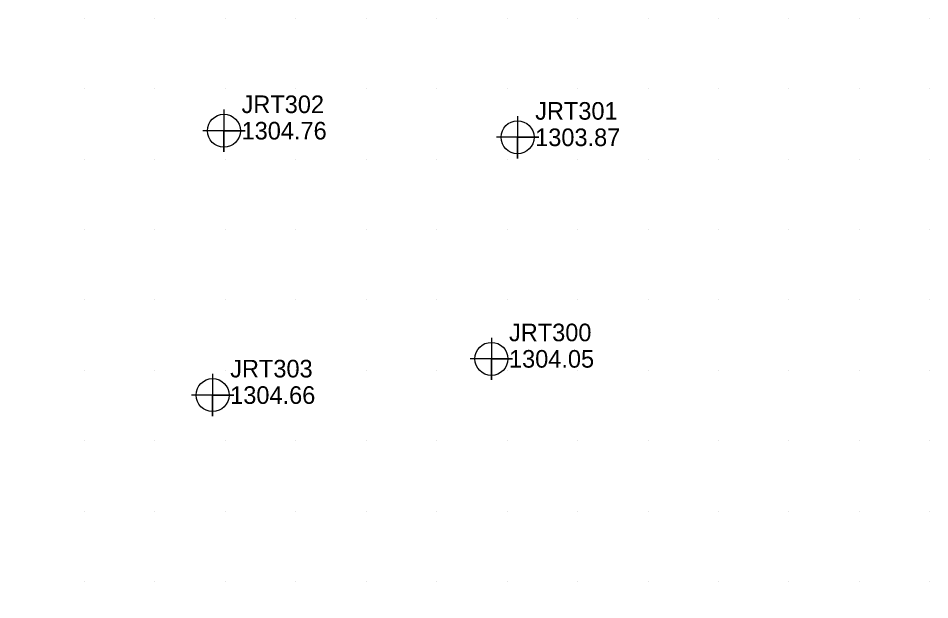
# Model space of a CAD drawing. Extents: x 1234484 to 1235382, y 695050 to 695510.
# Drawn here: x 1234800.6 to 1234930, y 695367.4 to 695450 of the extents above; entities that cross this region are included whole.
import ezdxf

# ---------------------------------------------------------------- set-up
doc = ezdxf.new("R2010")
doc.units = 0
for name, color, linetype in [('Exist DTM QL2 LIDAR Elevation Point', 7, 'Continuous'), ('Exist DTM Regular Point CELL', 7, 'Continuous'), ('Exist DTM Regular Point Cogo Elevation', 7, 'Continuous'), ('Exist DTM Regular Point Cogo Number', 7, 'Continuous'), ('Exist Roads EOP', 7, 'Continuous')]:
    doc.layers.add(name, color=color, linetype=linetype)

msp = doc.modelspace()

# ---------------------------------------------------------------- linework, layer by layer
at = {"layer": 'Exist DTM QL2 LIDAR Elevation Point'}
for p, q in [((1234810, 695450), (1234810, 695450)), ((1234820, 695450), (1234820, 695450)), ((1234830, 695450), (1234830, 695450)), ((1234840, 695450), (1234840, 695450)), ((1234850, 695450), (1234850, 695450)), ((1234860, 695450), (1234860, 695450)), ((1234870, 695450), (1234870, 695450)), ((1234880, 695450), (1234880, 695450)), ((1234890, 695450), (1234890, 695450)), ((1234900, 695450), (1234900, 695450)), ((1234910, 695450), (1234910, 695450)), ((1234920, 695450), (1234920, 695450)), ((1234930, 695450), (1234930, 695450)), ((1234810, 695440), (1234810, 695440)), ((1234820, 695440), (1234820, 695440)), ((1234830, 695440), (1234830, 695440)), ((1234840, 695440), (1234840, 695440)), ((1234850, 695440), (1234850, 695440)), ((1234860, 695440), (1234860, 695440)), ((1234870, 695440), (1234870, 695440)), ((1234880, 695440), (1234880, 695440)), ((1234890, 695440), (1234890, 695440)), ((1234900, 695440), (1234900, 695440)), ((1234910, 695440), (1234910, 695440)), ((1234920, 695440), (1234920, 695440)), ((1234930, 695440), (1234930, 695440)), ((1234810, 695430), (1234810, 695430)), ((1234820, 695430), (1234820, 695430)), ((1234830, 695430), (1234830, 695430)), ((1234840, 695430), (1234840, 695430)), ((1234850, 695430), (1234850, 695430)), ((1234860, 695430), (1234860, 695430)), ((1234870, 695430), (1234870, 695430)), ((1234880, 695430), (1234880, 695430)), ((1234890, 695430), (1234890, 695430)), ((1234900, 695430), (1234900, 695430)), ((1234910, 695430), (1234910, 695430)), ((1234920, 695430), (1234920, 695430)), ((1234930, 695430), (1234930, 695430)), ((1234810, 695420), (1234810, 695420)), ((1234820, 695420), (1234820, 695420)), ((1234830, 695420), (1234830, 695420)), ((1234840, 695420), (1234840, 695420)), ((1234850, 695420), (1234850, 695420)), ((1234860, 695420), (1234860, 695420)), ((1234870, 695420), (1234870, 695420)), ((1234880, 695420), (1234880, 695420)), ((1234890, 695420), (1234890, 695420)), ((1234900, 695420), (1234900, 695420)), ((1234910, 695420), (1234910, 695420)), ((1234920, 695420), (1234920, 695420)), ((1234930, 695420), (1234930, 695420)), ((1234810, 695410), (1234810, 695410)), ((1234820, 695410), (1234820, 695410)), ((1234830, 695410), (1234830, 695410)), ((1234840, 695410), (1234840, 695410)), ((1234850, 695410), (1234850, 695410)), ((1234860, 695410), (1234860, 695410)), ((1234870, 695410), (1234870, 695410)), ((1234880, 695410), (1234880, 695410)), ((1234890, 695410), (1234890, 695410)), ((1234900, 695410), (1234900, 695410)), ((1234910, 695410), (1234910, 695410)), ((1234920, 695410), (1234920, 695410)), ((1234930, 695410), (1234930, 695410)), ((1234810, 695400), (1234810, 695400)), ((1234820, 695400), (1234820, 695400)), ((1234830, 695400), (1234830, 695400)), ((1234840, 695400), (1234840, 695400)), ((1234850, 695400), (1234850, 695400)), ((1234860, 695400), (1234860, 695400)), ((1234870, 695400), (1234870, 695400)), ((1234880, 695400), (1234880, 695400)), ((1234890, 695400), (1234890, 695400)), ((1234900, 695400), (1234900, 695400)), ((1234910, 695400), (1234910, 695400)), ((1234920, 695400), (1234920, 695400)), ((1234930, 695400), (1234930, 695400)), ((1234810, 695390), (1234810, 695390)), ((1234820, 695390), (1234820, 695390)), ((1234830, 695390), (1234830, 695390)), ((1234840, 695390), (1234840, 695390)), ((1234850, 695390), (1234850, 695390)), ((1234860, 695390), (1234860, 695390)), ((1234870, 695390), (1234870, 695390)), ((1234880, 695390), (1234880, 695390)), ((1234890, 695390), (1234890, 695390)), ((1234900, 695390), (1234900, 695390)), ((1234910, 695390), (1234910, 695390)), ((1234920, 695390), (1234920, 695390)), ((1234930, 695390), (1234930, 695390)), ((1234810, 695380), (1234810, 695380)), ((1234820, 695380), (1234820, 695380)), ((1234830, 695380), (1234830, 695380)), ((1234840, 695380), (1234840, 695380)), ((1234850, 695380), (1234850, 695380)), ((1234860, 695380), (1234860, 695380)), ((1234870, 695380), (1234870, 695380)), ((1234880, 695380), (1234880, 695380)), ((1234890, 695380), (1234890, 695380)), ((1234900, 695380), (1234900, 695380)), ((1234910, 695380), (1234910, 695380)), ((1234920, 695380), (1234920, 695380)), ((1234930, 695380), (1234930, 695380)), ((1234810, 695370), (1234810, 695370)), ((1234820, 695370), (1234820, 695370)), ((1234830, 695370), (1234830, 695370)), ((1234840, 695370), (1234840, 695370)), ((1234850, 695370), (1234850, 695370)), ((1234860, 695370), (1234860, 695370)), ((1234870, 695370), (1234870, 695370)), ((1234880, 695370), (1234880, 695370)), ((1234890, 695370), (1234890, 695370)), ((1234900, 695370), (1234900, 695370)), ((1234910, 695370), (1234910, 695370)), ((1234920, 695370), (1234920, 695370)), ((1234930, 695370), (1234930, 695370))]:
    msp.add_line(p, q, dxfattribs=at)
at = {"layer": 'Exist DTM Regular Point CELL'}
for points in [[(1234829.792, 695437.031), (1234829.792, 695431.031), (1234829.792, 695434.031), (1234832.792, 695434.031), (1234826.792, 695434.031)], [(1234871.476, 695436.094), (1234871.476, 695430.094), (1234871.476, 695433.094), (1234874.476, 695433.094), (1234868.476, 695433.094)], [(1234867.76, 695404.636), (1234867.76, 695398.636), (1234867.76, 695401.636), (1234870.76, 695401.636), (1234864.76, 695401.636)], [(1234828.176, 695399.495), (1234828.176, 695393.495), (1234828.176, 695396.495), (1234831.176, 695396.495), (1234825.176, 695396.495)]]:
    msp.add_lwpolyline(points, dxfattribs=at)
for centre in [(1234829.792, 695434.031), (1234871.476, 695433.094), (1234867.76, 695401.636), (1234828.176, 695396.495)]:
    msp.add_circle(centre, 2.344, dxfattribs=at)
at = {"layer": 'Exist Roads EOP'}
msp.add_spline([(1234605.599, 695398.165), (1234601.696, 695381.855), (1234613.593, 695357.692), (1234658.916, 695353.52), (1234716.264, 695348.291), (1234770.499, 695343.743), (1234823.09, 695339.258), (1234845.762, 695337.371), (1234903.754, 695331.785), (1234928.613, 695329.389)], degree=3, dxfattribs=at)

# ---------------------------------------------------------------- texts
at = {"layer": 'Exist DTM Regular Point Cogo Elevation'}
for s, p in [('1304.76', (1234832.292, 695432.781)), ('1303.87', (1234873.976, 695431.844)), ('1304.05', (1234870.26, 695400.386)), ('1304.66', (1234830.676, 695395.245))]:
    msp.add_text(s, height=2.5, dxfattribs=at).set_placement(p)
at = {"layer": 'Exist DTM Regular Point Cogo Number'}
for s, p in [('JRT302', (1234832.292, 695436.531)), ('JRT301', (1234873.976, 695435.594)), ('JRT300', (1234870.26, 695404.136)), ('JRT303', (1234830.676, 695398.995))]:
    msp.add_text(s, height=2.5, dxfattribs=at).set_placement(p)

doc.saveas('drawing.dxf')
